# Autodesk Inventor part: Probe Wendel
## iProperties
Created: 2009-08
Part Number: Probe Wendel
Document SubType Name: Modeling
Designer: ak
Density: 1 g/cm^3
Author: ak
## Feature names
1. Coil1
2. Rectangular Pattern3
3. Extrusion1
